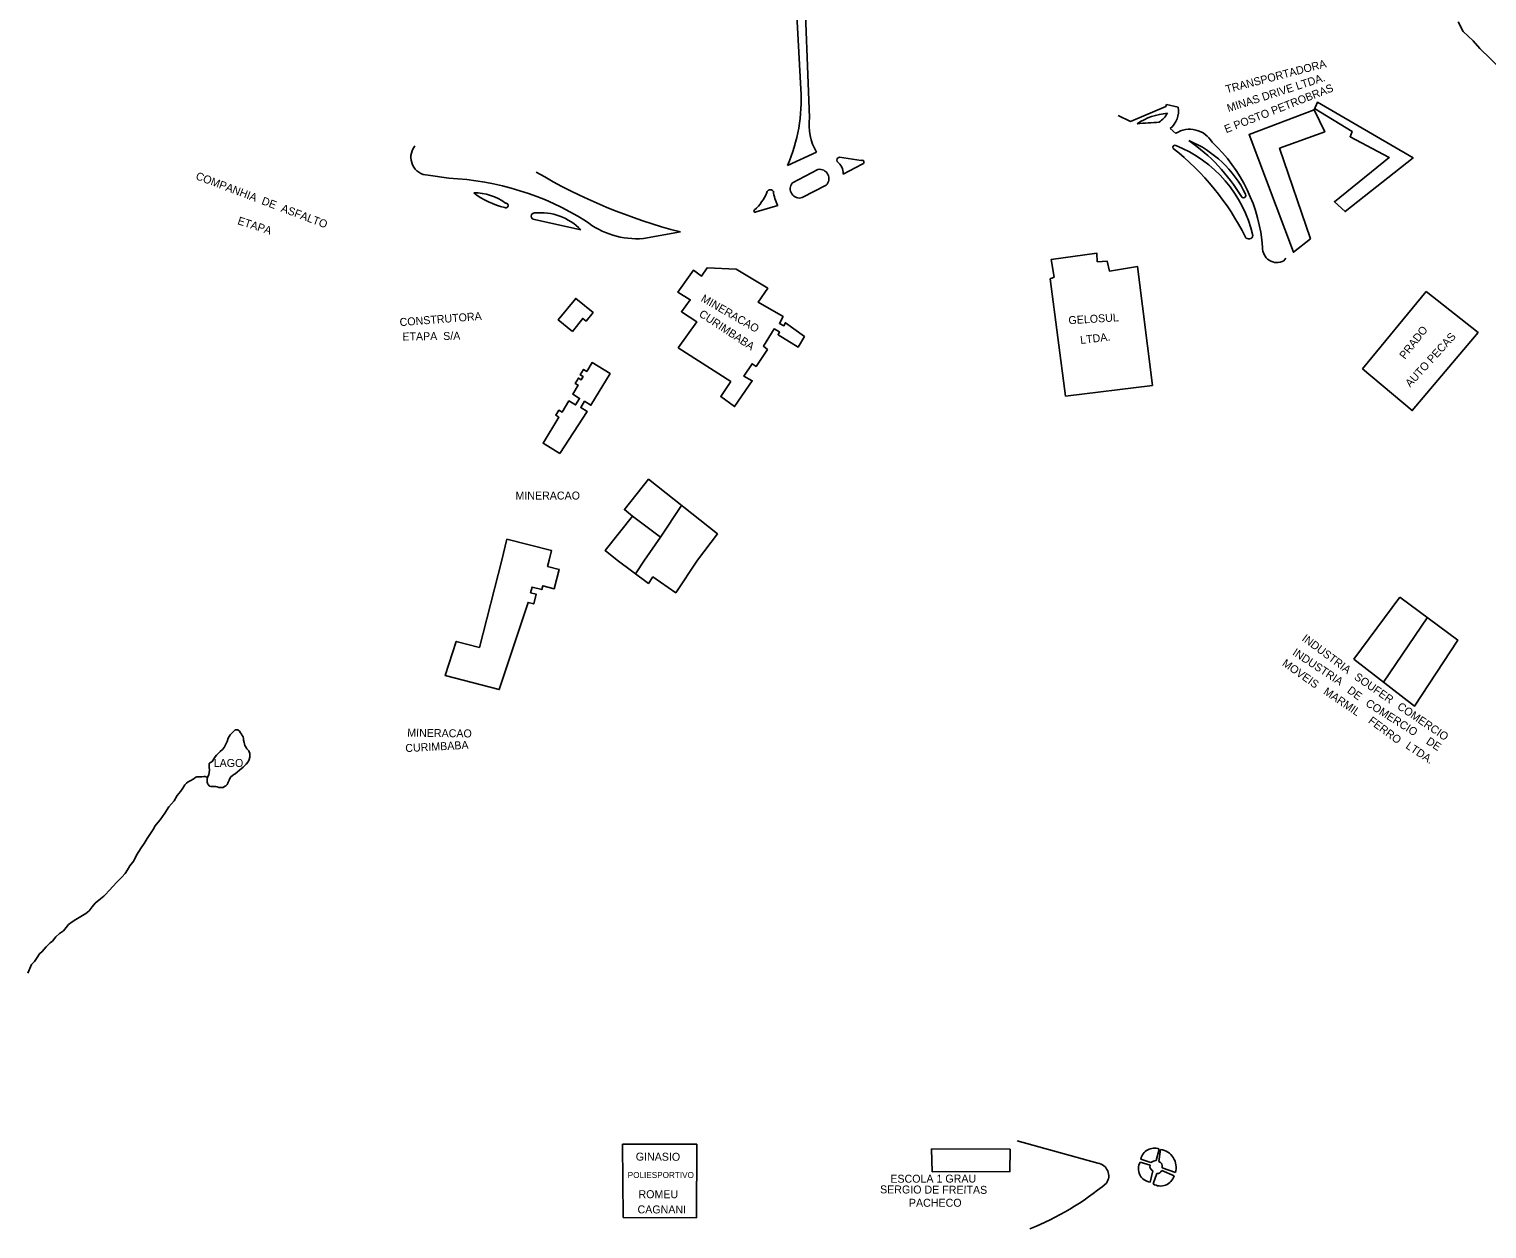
# Model space of a CAD drawing. Extents: x 325899 to 363134, y 7578590 to 7592502.
# Drawn here: x 333681 to 334413, y 7590166 to 7590768 of the extents above; entities that cross this region are included whole.
import ezdxf

# ---------------------------------------------------------------- set-up
doc = ezdxf.new("R2010")
doc.units = 0
for name, color, linetype in [('EDIFEXISTENT', 7, 'Continuous'), ('EDIFIDENTIF', 7, 'Continuous'), ('EDIFOBRAEXIS', 7, 'Continuous')]:
    doc.layers.add(name, color=color, linetype=linetype)

msp = doc.modelspace()

# ---------------------------------------------------------------- linework, layer by layer
at = {"layer": 'EDIFEXISTENT'}
for points in [[(334324.84, 7590663.26), (334316.33, 7590656.49), (334294.09, 7590715.54), (334326.75, 7590728.04), (334328.39, 7590731.81), (334376.43, 7590703.84), (334342.3, 7590676.87), (334336.91, 7590681.85), (334364.49, 7590703.99), (334344.77, 7590714.47), (334345.86, 7590717.07), (334326.99, 7590728.6)], [(334326.75, 7590728.04), (334332.07, 7590716.95), (334309.42, 7590708.67), (334324.84, 7590663.26)], [(334201.8, 7590584.27), (334194.17, 7590643.09), (334196.14, 7590644), (334194.6, 7590652.82), (334217.57, 7590656.07), (334217.81, 7590651.73), (334222.86, 7590652), (334223.89, 7590647.04), (334238.08, 7590649.31), (334245.52, 7590589.62)], [(334007.31, 7590608.56), (334016.69, 7590621.48), (334008.94, 7590626.57), (334013.41, 7590632.64), (334007.18, 7590636.4), (334015.06, 7590647.5), (334019.1, 7590644.54), (334021.83, 7590648.58), (334036.51, 7590648.03), (334052.3, 7590638.39), (334047.48, 7590631.5), (334060.03, 7590624.21), (334058.15, 7590620.77), (334060.44, 7590619.55), (334061.17, 7590621.07), (334070.74, 7590614.17), (334067.59, 7590608.87), (334057.48, 7590615.08), (334058.21, 7590616.48), (334055.53, 7590618.01), (334050.14, 7590609.33), (334052.14, 7590607.62), (334046.47, 7590599.2), (334044.48, 7590600.53), (334040.24, 7590594.35), (334044.55, 7590591.95), (334035.64, 7590579.01), (334028.75, 7590584.03), (334033.71, 7590591.61)], [(333954.25, 7590616.71), (333947.1, 7590622.54), (333955.91, 7590633.32), (333964.62, 7590626.22), (333961.1, 7590621.9), (333959.45, 7590623.25), (333954.25, 7590616.71)], [(334383.04, 7590636.75), (334409.07, 7590616.17), (334376.04, 7590577.02), (334351.02, 7590598.01)], [(334351.02, 7590598.01), (334383.04, 7590636.75)], [(334033.71, 7590591.61), (334007.31, 7590608.56)], [(333947.97, 7590555.42), (333939.51, 7590560.56), (333947.47, 7590573.67), (333945.88, 7590574.64), (333947.43, 7590577.19), (333949.03, 7590576.21), (333952.47, 7590581.87), (333955.82, 7590579.83), (333957.8, 7590583.09), (333954.36, 7590585.18), (333957.05, 7590589.77), (333955.62, 7590590.63), (333957.22, 7590593.27), (333958.62, 7590592.42), (333959.59, 7590594.02), (333958.19, 7590594.87), (333959.86, 7590597.64), (333961.43, 7590596.69), (333964.09, 7590601.08), (333973.16, 7590595.58), (333963.51, 7590579.68), (333960.33, 7590581.65), (333958.4, 7590578.46), (333961.59, 7590576.53), (333947.97, 7590555.42)], [(334245.52, 7590589.62), (334201.8, 7590584.27)], [(333976.75, 7590501.91), (333970.74, 7590506.73), (333984.42, 7590524.04), (333980.37, 7590527.28), (333992.5, 7590542.51), (334027.09, 7590515.05), (334016.97, 7590501.91)], [(333984.38, 7590523.99), (333998.42, 7590513.38)], [(333990.35, 7590501.91), (333998.42, 7590513.38), (334009.03, 7590529.39)], [(333918.79, 7590501.91), (333921.3, 7590512.39), (333943.71, 7590506.8), (333942.56, 7590501.91)], [(333942.56, 7590501.91), (333941.74, 7590498.78), (333947.61, 7590497.26), (333945.1, 7590487.58), (333939.29, 7590489.09), (333938.79, 7590487.15), (333933.95, 7590488.4), (333933.2, 7590485.5), (333936.1, 7590484.75), (333934.85, 7590479.91), (333931.94, 7590480.66), (333917.5, 7590436.89), (333890.39, 7590443.91), (333895.88, 7590461.09), (333907.49, 7590458.07), (333918.79, 7590501.91)], [(334016.97, 7590501.91), (334006.16, 7590485.56), (333994.65, 7590493.52), (333992.37, 7590490.24), (333976.75, 7590501.91)], [(333990.35, 7590501.91), (333985.94, 7590495.04)], [(334369.77, 7590483.39), (334398.83, 7590461.79), (334377.14, 7590428.62), (334346.62, 7590452.22)], [(334346.62, 7590452.22), (334369.77, 7590483.39)], [(334383.42, 7590472.97), (334361.51, 7590440.6)], [(333979.69, 7590171.89), (333979.46, 7590208.7), (334016.64, 7590208.7), (334016.51, 7590171.73)], [(334134.62, 7590206.35), (334174.02, 7590206.16), (334173.91, 7590194.97), (334134.91, 7590194.76)], [(334134.91, 7590194.76), (334134.62, 7590206.35)], [(334016.51, 7590171.73), (333979.69, 7590171.89)]]:
    msp.add_lwpolyline(points, dxfattribs=at)
at = {"layer": 'EDIFOBRAEXIS'}
for points in [[(334068.94, 7590738.33), (334065.68, 7590797.21), (334070.49, 7590797.56), (334073.25, 7590724.09)], [(334399.02, 7590772.12), (334401.6, 7590767.32), (334406.59, 7590762.65), (334409.99, 7590758.75), (334415.36, 7590753.62), (334421.71, 7590747.01), (334425.94, 7590740.73), (334425.94, 7590740.73)], [(334258.5, 7590729.36), (334252.66, 7590730.62), (334252.18, 7590729.71), (334234.55, 7590722.15), (334228.28, 7590725.1)], [(334257.24, 7590716.18), (334254.41, 7590718.57)], [(333874.87, 7590709.62), (333875.15, 7590709.93)], [(334076.8, 7590706.65), (334062.22, 7590700.11)], [(334088.28, 7590704.19), (334099.22, 7590702.56)], [(334099.82, 7590700.74), (334090.2, 7590695.71)], [(333892.09, 7590693.64), (333881.71, 7590695.12)], [(334064.7, 7590691.33), (334077.55, 7590698.06)], [(334081.71, 7590690.09), (334069.64, 7590683.9)], [(334057.35, 7590680.01), (334046.52, 7590676.8)], [(333935.18, 7590672.86), (333958.53, 7590667.7)], [(334008.49, 7590666.71), (333989.86, 7590663.41)], [(334312.47, 7590653.48), (334311.5, 7590652.21)], [(333680.79, 7590294.49), (333682.6, 7590298.82), (333684.01, 7590300.41), (333685.4, 7590302.44), (333686.56, 7590304.2), (333687.98, 7590305.42), (333689.98, 7590307.79), (333691.95, 7590309.7), (333693.17, 7590310.64), (333694.86, 7590312.73), (333696.56, 7590314.41), (333698.61, 7590315.83), (333700.05, 7590317.54), (333701.16, 7590318.94), (333703.04, 7590320.32), (333704.79, 7590321.51), (333707.32, 7590322.92), (333709.83, 7590324.57), (333711.47, 7590325.92), (333713.09, 7590327.81), (333714.48, 7590329.61), (333717.24, 7590331.83), (333718.84, 7590333.18), (333719.7, 7590334.07), (333721.62, 7590336.13), (333723.57, 7590338.19), (333725.31, 7590340), (333727.69, 7590342.57), (333729.54, 7590344.58), (333730.78, 7590346.36), (333731.89, 7590348.52), (333733.96, 7590350.99), (333735.32, 7590353.81), (333737.67, 7590357.5), (333739.21, 7590359.66), (333740.73, 7590362.18), (333742.67, 7590365.13), (333743.99, 7590367.19), (333744.54, 7590368.31), (333747.17, 7590371.51), (333749.6, 7590374.92), (333751.57, 7590378.13), (333754.17, 7590381.13), (333755.69, 7590383.67), (333757.36, 7590385.76), (333758.55, 7590387.44), (333759.66, 7590389.14), (333760.44, 7590389.93), (333761.28, 7590390.54), (333762.67, 7590391.26), (333763.76, 7590391.89), (333764.27, 7590392.28), (333765.18, 7590392.91), (333765.61, 7590393.07), (333766.88, 7590393.17), (333768.05, 7590393.2), (333769.14, 7590393.28), (333769.85, 7590393.23), (333770.69, 7590392.93), (333770.97, 7590392.96), (333771.55, 7590394.18), (333771.82, 7590395.27), (333771.99, 7590396.51), (333771.87, 7590397.94), (333771.73, 7590398.85), (333771.73, 7590399.51), (333771.88, 7590399.79), (333772.04, 7590399.94), (333772.52, 7590400.25), (333772.8, 7590400.45), (333773.35, 7590400.78), (333774.49, 7590402.61), (333774.79, 7590403.1), (333775.53, 7590403.96), (333776.51, 7590405.08), (333777.27, 7590405.82), (333778.44, 7590406.76), (333779.3, 7590407.88), (333780.03, 7590409.18), (333780.78, 7590410.93), (333781.39, 7590412.53), (333782.37, 7590414.18), (333783.38, 7590415.25), (333783.99, 7590415.92), (333784.45, 7590416.3), (333784.93, 7590416.68), (333785.18, 7590416.73), (333785.74, 7590416.73), (333786.25, 7590416.68), (333786.96, 7590416.03), (333787.6, 7590415.22), (333788.01, 7590414.58), (333788.44, 7590413.9), (333788.85, 7590413.14), (333789, 7590412.2), (333789.08, 7590411.54), (333789.31, 7590410.32), (333789.52, 7590409.64), (333789.77, 7590408.9), (333790, 7590408.42), (333790.51, 7590407.48), (333790.77, 7590407.23), (333791.28, 7590406.7), (333791.71, 7590406.12), (333791.92, 7590405.61), (333792.17, 7590404.8), (333792.28, 7590403.86), (333792.28, 7590403), (333791.88, 7590401.8), (333791.32, 7590400.71), (333790.39, 7590399.49), (333788.94, 7590397.94), (333787.05, 7590396.43), (333785.86, 7590395.44), (333784.84, 7590394.67), (333784.11, 7590394.22), (333783.32, 7590393.63), (333782.72, 7590393.07), (333782.16, 7590392.2), (333781.76, 7590391.44), (333781.33, 7590390.5), (333781.13, 7590390.02), (333780.82, 7590389.23), (333780.22, 7590388.65), (333779.58, 7590388.24), (333778.8, 7590387.78), (333777.38, 7590387.72), (333776.69, 7590387.82), (333775.83, 7590388.18), (333775.07, 7590388.25), (333773.97, 7590388.25), (333773.06, 7590388.24), (333772.63, 7590388.27), (333772.04, 7590388.49), (333771.79, 7590388.65), (333771.79, 7590388.65), (333771.46, 7590389.1), (333771.18, 7590389.51), (333770.95, 7590389.91), (333770.8, 7590390.39), (333770.74, 7590390.8), (333770.74, 7590391.15), (333770.74, 7590391.31), (333770.79, 7590391.59), (333770.84, 7590391.81), (333770.97, 7590392.96)], [(334177.64, 7590210.3), (334218.13, 7590199.14)], [(334244.77, 7590199.42), (334239.73, 7590201.23)], [(334248.87, 7590206.25), (334247.36, 7590200.44)], [(334248.69, 7590200.01), (334249.59, 7590205.99)], [(334239.33, 7590199.67), (334244.39, 7590198.1)], [(334245.79, 7590195.33), (334244.32, 7590189.65)], [(334245.89, 7590188.74), (334247.69, 7590194)], [(334250.17, 7590195.47), (334256.42, 7590192.75)], [(334257.04, 7590194.41), (334250.45, 7590196.89)]]:
    msp.add_lwpolyline(points, dxfattribs=at)
for centre, radius, start, end in [((333987.09, 7590733.03), 82.03, 336.34061, 3.70839), ((334247.07, 7590727.52), 11.57, 309.32726, 9.12579), ((334101.21, 7590720.7), 28.16, 173.07622, 209.91546), ((334255.51, 7590694.67), 31.69, 94.45283, 123.85421), ((334276.82, 7590261.37), 461.26, 93.46653, 94.84584), ((334241.59, 7590732.69), 13.14, 303.96558, 330.73157), ((334264.22, 7590705.25), 12.97, 29.94911, 122.54527), ((333882.19, 7590704.21), 9.1, 143.56955, 266.97353), ((334256.95, 7590709.06), 1.13, 90.70397, 203.32362), ((334175.38, 7590605.96), 130.48, 26.4701, 51.885), ((334233.39, 7590650.43), 64.24, 12.9608, 68.50061), ((334242.82, 7590661.84), 54.86, 25.71971, 67.46789), ((334212.47, 7590637.98), 90.52, 30.85935, 55.42442), ((334220.57, 7590652.8), 80.53, 4.43262, 47.03436), ((334078.34, 7590693.4), 4.73, 315.41262, 99.56463), ((334088.65, 7590702.68), 1.56, 103.7516, 204.63896), ((334082.54, 7590695.96), 7.67, 358.14257, 52.24243), ((334099.7, 7590701.71), 0.976, 277.38801, 119.02372), ((333885.56, 7590551.11), 142.67, 58.13892, 87.37494), ((334075.76, 7590931.32), 273.02, 239.22039, 255.73675), ((334068.31, 7590688.37), 4.67, 140.57188, 286.52424), ((333905.14, 7590660.28), 26.01, 53.44409, 90.99544), ((333930.89, 7590721.3), 43.73, 233.18486, 255.87375), ((334028.88, 7590696.1), 24.92, 312.60662, 337.10655), ((334053.66, 7590685.99), 1.87, 38.13936, 167.15067), ((334074.82, 7590689.35), 19.81, 186.39779, 208.1299), ((334291.24, 7590684.98), 1.21, 207.92664, 33.74), ((333920.75, 7590679.97), 1.21, 243.86044, 95.72668), ((333935.26, 7590674.53), 1.67, 90.10543, 267.4033), ((333937.99, 7590647.59), 28.75, 44.41356, 95.46822), ((334046.01, 7590677.18), 0.635, 113.92977, 323.6307), ((333986.41, 7590703.9), 40.64, 231.06311, 274.8659), ((334293.95, 7590665.2), 2.08, 211.46467, 349.79108), ((334308.01, 7590658.47), 7.16, 175.58683, 299.16225), ((334246.43, 7590199.87), 6.83, 69.04586, 168.52305), ((334247.46, 7590196.36), 4.08, 91.39637, 131.29954), ((334248.43, 7590197.05), 9.01, 342.9405, 82.59361), ((334217.16, 7590192.8), 6.42, 324.82638, 81.31728), ((334245.27, 7590196.37), 6.79, 150.91383, 261.97316), ((334246.5, 7590197.43), 2.22, 162.50478, 251.14108), ((334248.12, 7590196.11), 2.15, 258.46482, 342.71973), ((334247.82, 7590197.46), 2.69, 347.83567, 71.12567), ((334131.42, 7590298.28), 142.12, 291.65963, 309.80464), ((334249.6, 7590194.82), 7.13, 238.6196, 343.05626)]:
    msp.add_arc(centre, radius, start, end, dxfattribs=at)

# ---------------------------------------------------------------- texts
at = {"layer": 'EDIFIDENTIF'}
for s, rotation, p in [('TRANSPORTADORA', 14.66629, (334282.84, 7590736.28)), ('MINAS DRIVE LTDA.', 17.90916, (334283.72, 7590726.77)), ('E POSTO PETROBRAS', 21.37827, (334282.56, 7590716.22)), ('COMPANHIA  DE  ASFALTO', 339.26603, (333764.69, 7590693.24)), ('ETAPA', 342.1067, (333785.73, 7590670.65)), ('MINERACAO', 330.03779, (334018.44, 7590632.12)), ('CONSTRUTORA', 4.42881, (333867.6, 7590619.35)), ('CURIMBABA', 326.57661, (334017.43, 7590624.55)), ('GELOSUL', 3.46178, (334203.48, 7590620.32)), ('PRADO', 52.05001, (334372.32, 7590602.49)), ('ETAPA  S/A', 0.77231, (333868.84, 7590612.16)), ('LTDA.', 6.71543, (334209.48, 7590610.4)), ('AUTO PECAS', 47.63451, (334374.98, 7590588.43)), ('INDUSTRIA', 323.28991, (334320.25, 7590461.83)), ('INDUSTRIA', 326.67502, (334315.5, 7590454.59)), ('MOVEIS', 324.77591, (334310.32, 7590449.28)), ('SOUFER', 325.29731, (334346.49, 7590442.39)), ('MARMIL', 325.99876, (334331.06, 7590435.02)), ('DE', 323.45761, (334342.98, 7590435.74)), ('COMERCIO', 327.74865, (334352.21, 7590429.06)), ('COMERCIO', 325.87141, (334368.11, 7590427.55)), ('FERRO', 323.52873, (334353.58, 7590420.52)), ('MINERACAO', 359.25229, (333871.27, 7590413.3)), ('DE', 326.84555, (334382.63, 7590410.01)), ('CURIMBABA', 3.02292, (333870.4, 7590405.52)), ('LTDA.', 326.18838, (334372.37, 7590407.77)), ('GINASIO', 359.69813, (333986.04, 7590200.47)), ('ESCOLA 1 GRAU', 0.13388, (334113.89, 7590189.33)), ('SERGIO DE FREITAS', 359.72814, (334108.73, 7590184.01)), ('PACHECO', 0.07182, (334123.22, 7590177.26)), ('CAGNANI', 359.87333, (333986.93, 7590173.95))]:
    msp.add_text(s, height=4, rotation=rotation, dxfattribs=at).set_placement(p)
for s, height, p in [('MINERACAO', 4, (333925.62, 7590532.33)), ('LAGO', 4, (333774.07, 7590398.07)), ('POLIESPORTIVO', 3.0633, (333982.01, 7590191.69)), ('ROMEU', 4, (333987.41, 7590181.58))]:
    msp.add_text(s, height=height, dxfattribs=at).set_placement(p)

doc.saveas('drawing.dxf')
